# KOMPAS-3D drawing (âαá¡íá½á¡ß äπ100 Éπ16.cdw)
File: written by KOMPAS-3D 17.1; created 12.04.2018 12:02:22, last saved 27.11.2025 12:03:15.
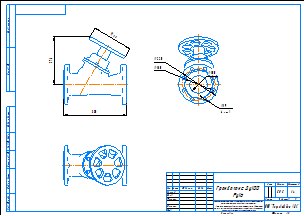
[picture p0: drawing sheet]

Sheet 1: A3, landscape

Title block, sheet 1: name: Гранбаланс Ду100 / Ру16; material: Сталь 20  ГОСТ 1050-88; mass: 50,5; sheets: 1; sheet format: A3; stored path: C:\Users\kka\KOMPAS_Work\!Trash\КМ125 КМ127 КМ225Ф Двухходовые клапана\КМ125Ф + PSL\KOMPAS 2D\Гранрег КМ125Ф Ду32 Ру16.cdw

Views: Спереди 1, Спереди, Проекционный вид 2, Проекционный вид 3
Referenced files in C:\Users\mipv\Desktop\КБЧ\Имеющиеся\: Гранбаланс Ду100 Ру16  серия 10.m3d
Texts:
  kka
  adl
  Рама для чертежей
  Лит-Масса-Масштаб
  Материал-Предприятие
  Масштаб
  Изм.
  Лист
  № докум.
  Подп.
  Дата
  Лит.
  Разраб.
  Пров.
  Т.контр.
  Листов
  Внимание! Данный продукт является объектом авторского права ООО «Торговый Дом АДЛ».
  Запрещается изменение, копирование, распространение
  (в том числе путем копирования на другие сайты и ресурсы в Интернете)
  или любое иное использование информации и объектов без предварительного
  согласия правообладателя (ООО «Торговый Дом АДЛ»).
  Н.контр.
  Утв.
  ООО "Торговый дом АДЛ"
  Изменение
  Номер документа
  Подпись
  Обозначение документа
  Наименование изделия
  Масса изделия по ГОСТ 2.109-73
  Порядковый номер листа
  Общее количество листов в документе
  Характер работы, выполненной лицом, подписавшим документ
  Наименование или индекс предприятия, выпускающего документ
  Инв. № подл.
  Подп. и дата
  Взам. инв. №
  Инв. № дубл.
  Инвентарный номер подлинника по ГОСТ 2.501-68
  Подпись принявшего подлинник в отдел технической документации
  Инвентарный номер подлинника, взамен которого выпущен данный подлинник
  Инвентарный номер дубликата по ГОСТ 2.502-68
  Подпись принявшего дубликат в отдел технической документации
  Справ. №
  Перв. примен.
  Обозначение документа, взамен или на основании которого выпущен данный документ
  Обозначение документа, в котором впервые записан данный документ
  Подпись лица, копировавшего чертеж
  Обозначение формата листа
  !Рама для чертежа
Dimensions and other numbers on the sheet: 350; 276; 220; 180; 100; 19; 4 отв.; 1:4; 1; 50,5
